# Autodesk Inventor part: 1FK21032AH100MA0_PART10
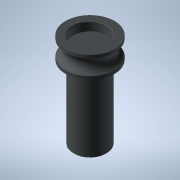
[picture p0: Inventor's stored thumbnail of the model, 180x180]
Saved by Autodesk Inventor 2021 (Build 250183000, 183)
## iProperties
Created: 2025-04
Part Number: 1FK21032AH100MA0_PART10
Material: Generic
Catalog Web Link: www.3dfindit.com
Description: -Servo synchronous motor
Document SubType Name: Modeling
Designer: psAdmin
Mass: 6.43867 g
Surface Area: 29.6592 cm^2
Volume: 6.43867 cm^3
Density: 1 g/cm^3
Appearance: PSOLRGB-212-217-219
Category: PARTsolutions
Title: 1FK21032AH100MA0_PART10
Author: Cadenas PARTsolutions
Comments: Servo synchronous motor
Sending System: PARTsolutions
Preprocessor: ST-DEVELOPER v19.3
PSOL_IDENT_0: {$CADENAS_DATA/23d-libs/siemens_ag/_cat_/12/33/1fk21032ah100ma0.prj},216 {VTYP=3D},{NB=1FK21032AH100
PSOL_IDENT_1: MA0_PART10},{LINA=1FK21032AH100MA0_PART10},{NN=1FK21032AH100MA0_PART10},{NOPRJ=TRUE},{DATE=19.08.202
PSOL_IDENT_2: 5 14:00:27},{GEOMDATE=30.07.2025 02:02:58},{VERSION=},{LINEID=10},{WBVAR=},{WBNUMERIC=}  {NB=1FK2103
PSOL_IDENT_3: 2AH100MA0_PART10},{LINA=1FK21032AH100MA0_PART10},{KT=DUMMY},{PREVIEW=../../../_pool_/d3/78/p_d211_xx
PSOL_IDENT_4: _00934j.png},{DESCSHORT=SIMOTICS S-1FK2 HD, SINAMICS S210 3AC 400V-480V, 0.59 Nm, 4500 rpm},{DESCLON
PSOL_IDENT_5: G=SIMOTICS S-1FK2 HD servo motor M0=0.64 Nm; PN = 0.28 kW at nN=4500 rpm (380-480 V); PN = 0.167 kW
PSOL_IDENT_6: at nN=2500 rpm (200-240 V); with holding brake; degree of protection IP64; cylindrical shaft D14 x 3
PSOL_IDENT_7: 0 mm; absolute encoder 22-bit + 12-bit multiturn (encoder AM22DQC); with OCC interface; plug size M1
PSOL_IDENT_8: 7, rotatable; SIMOTICS S-1FK2 servomotorfor a wide range of uses in industrial environments. SIMOTIC
PSOL_IDENT_9: S S‑1FK2 servomotors are compact synchronous motors with a high dynamic performance that set themsel
PSOL_IDENT_10: ves apart as a result of their high power density, degree of protection and overload capability. The
PSOL_IDENT_11: motors are available in two variants: as High Dynamic variant (highest dynamic performance as a res
PSOL_IDENT_12: ult of the low intrinsic moment of inertia for applications demanding a high dynamic performance wit
PSOL_IDENT_13: h low moved masses) - and as Compact variant (precise and stable closed-loop control for medium up t
PSOL_IDENT_14: o large moved masses as a result of a medium intrinsic moment of inertia). SIMOTICSS‑1FK2 servomotor
PSOL_IDENT_15: s fully exploit their strengths in a system with the SINAMICSS210 frequency converter and simple con
PSOL_IDENT_16: nection using the one cable connection (OCC). Advantages include the short control and positioning t
PSOL_IDENT_17: imes, fast and precise correction of disturbing quantities as well as stable control with a high dyn
PSOL_IDENT_18: amic performance. The servo motors can be configured to address a wide range of requirements. For ex
PSOL_IDENT_19: ample with and without holding brake, IP64 or IP65 degree of protection, singleturn or multiturn abs
PSOL_IDENT_20: olute encoders - to name just a few. Further, the servomotors are available in different shaft heigh
PSOL_IDENT_21: ts extending from 20 to 100. A shaft sealing ring is available to achieve an IP65 degree of protecti
PSOL_IDENT_22: on and for subsequent mounting at the motor or as spare part. SIMOTICS - the optimum motor for each
PSOL_IDENT_23: and every motion control application.},{INTNO=195125315563},{SUPPLIERALTNO=1FK2103-2AH10-0MA0},{MANU
PSOL_IDENT_24: ID=1FK21032AH100MA0},{MANUNAME=Siemens},{MANUTYPEDESC=SYNCHRONOUS MOTOR 1FK2 HD 0,64 NM},{AAU732=SIM
PSOL_IDENT_25: OTICS},{AAO057=S-1FK2},{AAU734=SIMOTICS S-1FK2 HD servo motor M0=0.64 Nm; PN = 0.28 kW at nN=4500 rp
PSOL_IDENT_26: m (380-480 V); PN = 0.167 kW at nN=2500 rpm (200-240 V); with holding brake; degree of protection IP
PSOL_IDENT_27: 64; cylindrical shaft D14 x 30 mm; absolute encoder 22-bit + 12-bit multiturn (encoder AM22DQC); wit
PSOL_IDENT_28: h OCC interface; plug size M17, rotatable;},{AAW338=SYNCHRONOUS MOTOR 1FK2 HD 0,64 NM},{AAO742=SIMOT
PSOL_IDENT_29: ICS},{AAO663=4034106444723},{NOCUPEROU=1},{PRICEQUANTITY=1},{QUANTITYMIN=1},{QUANTITYINT=1},{CTN=850
PSOL_IDENT_30: 15100},{COO=RO},{AAO676=1FK2103-2AH10-0MA0},{AAO677=Siemens AG},{ORDERUNIT=C62},{CONTENTUNIT=C62}
NB: 1FK21032AH100MA0_PART10
NT: Servo synchronous motor
NBSYN: $MANUID._PART10
LINA: 1FK21032AH100MA0_PART10
CATALOG: SIEMENS
PREVIEW: ../../../_pool_/d3/78/p_d211_xx_00934j.png
DESCSHORT: SIMOTICS S-1FK2 HD, SINAMICS S210 3AC 400V-480V, 0.59 Nm, 4500 rpm
DESCLONG: SIMOTICS S-1FK2 HD servo motor M0=0.64 Nm; PN = 0.28 kW at nN=4500 rpm (380-480 V); PN = 0.167 kW at nN=2500 rpm (200-240 V); with holding brake; degree of prot
INTNO: 195125315563
SUPPLIERALTNO: 1FK2103-2AH10-0MA0
MANUID: 1FK21032AH100MA0
MANUNAME: Siemens
MANUTYPEDESC: SYNCHRONOUS MOTOR 1FK2 HD 0,64 NM
AAU732: SIMOTICS
AAO057: S-1FK2
AAU734: SIMOTICS S-1FK2 HD servo motor M0=0.64 Nm; PN = 0.28 kW at nN=4500 rpm (380-480 V); PN = 0.167 kW at nN=2500 rpm (200-240 V); with holding brake; degree of prot
AAW338: SYNCHRONOUS MOTOR 1FK2 HD 0,64 NM
AAO742: SIMOTICS
AAO663: 4034106444723.0
NOCUPEROU: 1
PRICEQUANTITY: 1
QUANTITYMIN: 1
QUANTITYINT: 1
CTN: 85015100
COO: RO
ARTICLENO: 1FK21032AH100MA0_PART10
BOMINFO: 1FK21032AH100MA0_PART10
CREATOR: CADENAS GmbH
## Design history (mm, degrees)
feature "2025_04_17_15_06_16_0705"
body "Solid1"
